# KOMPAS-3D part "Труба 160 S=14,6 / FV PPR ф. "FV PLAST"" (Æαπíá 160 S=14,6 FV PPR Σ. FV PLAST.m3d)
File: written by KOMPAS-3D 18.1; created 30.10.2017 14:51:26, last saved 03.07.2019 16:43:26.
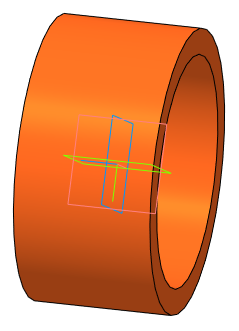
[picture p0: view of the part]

Document properties: Автор: Милов; Организация: Милов; Полное имя файла: D:\Magna\Магна Ins\Магна ins 10\М10-00.00.000\3Д\Труба 160 S=14,6 FV PPR ф. FV PLAST.m3d

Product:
- Part/product: Труба 160 S=14,6 / FV PPR ф. "FV PLAST"
    Материал: Полипропилен  ГОСТ 26996-86 (density 900 kg/m3)
    Масса: 0.720263
    Раздел спецификации: Прочие изделия
    Примечание: м

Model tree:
1. Эскиз:1
2. Операция выдавливания:1  (labels: Полипропилен  ГОСТ 26996-86)
     Расстояние 2 = 40

Expressions: D-S*2
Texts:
  Body Specification ( left align )
  Body Specificaton ( centered )

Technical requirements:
  Gost Type A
